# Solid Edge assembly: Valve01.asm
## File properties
Author: ptcarter
Template: NORMAL.ASM
Last saved by: ptcarter
Revision: 38
Application: Solid Edge
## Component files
RValve.par
LValve.par
ValveShaft.par
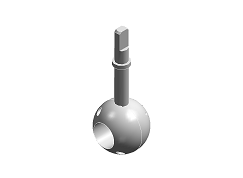
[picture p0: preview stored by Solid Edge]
